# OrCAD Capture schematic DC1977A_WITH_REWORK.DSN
size A; title: -
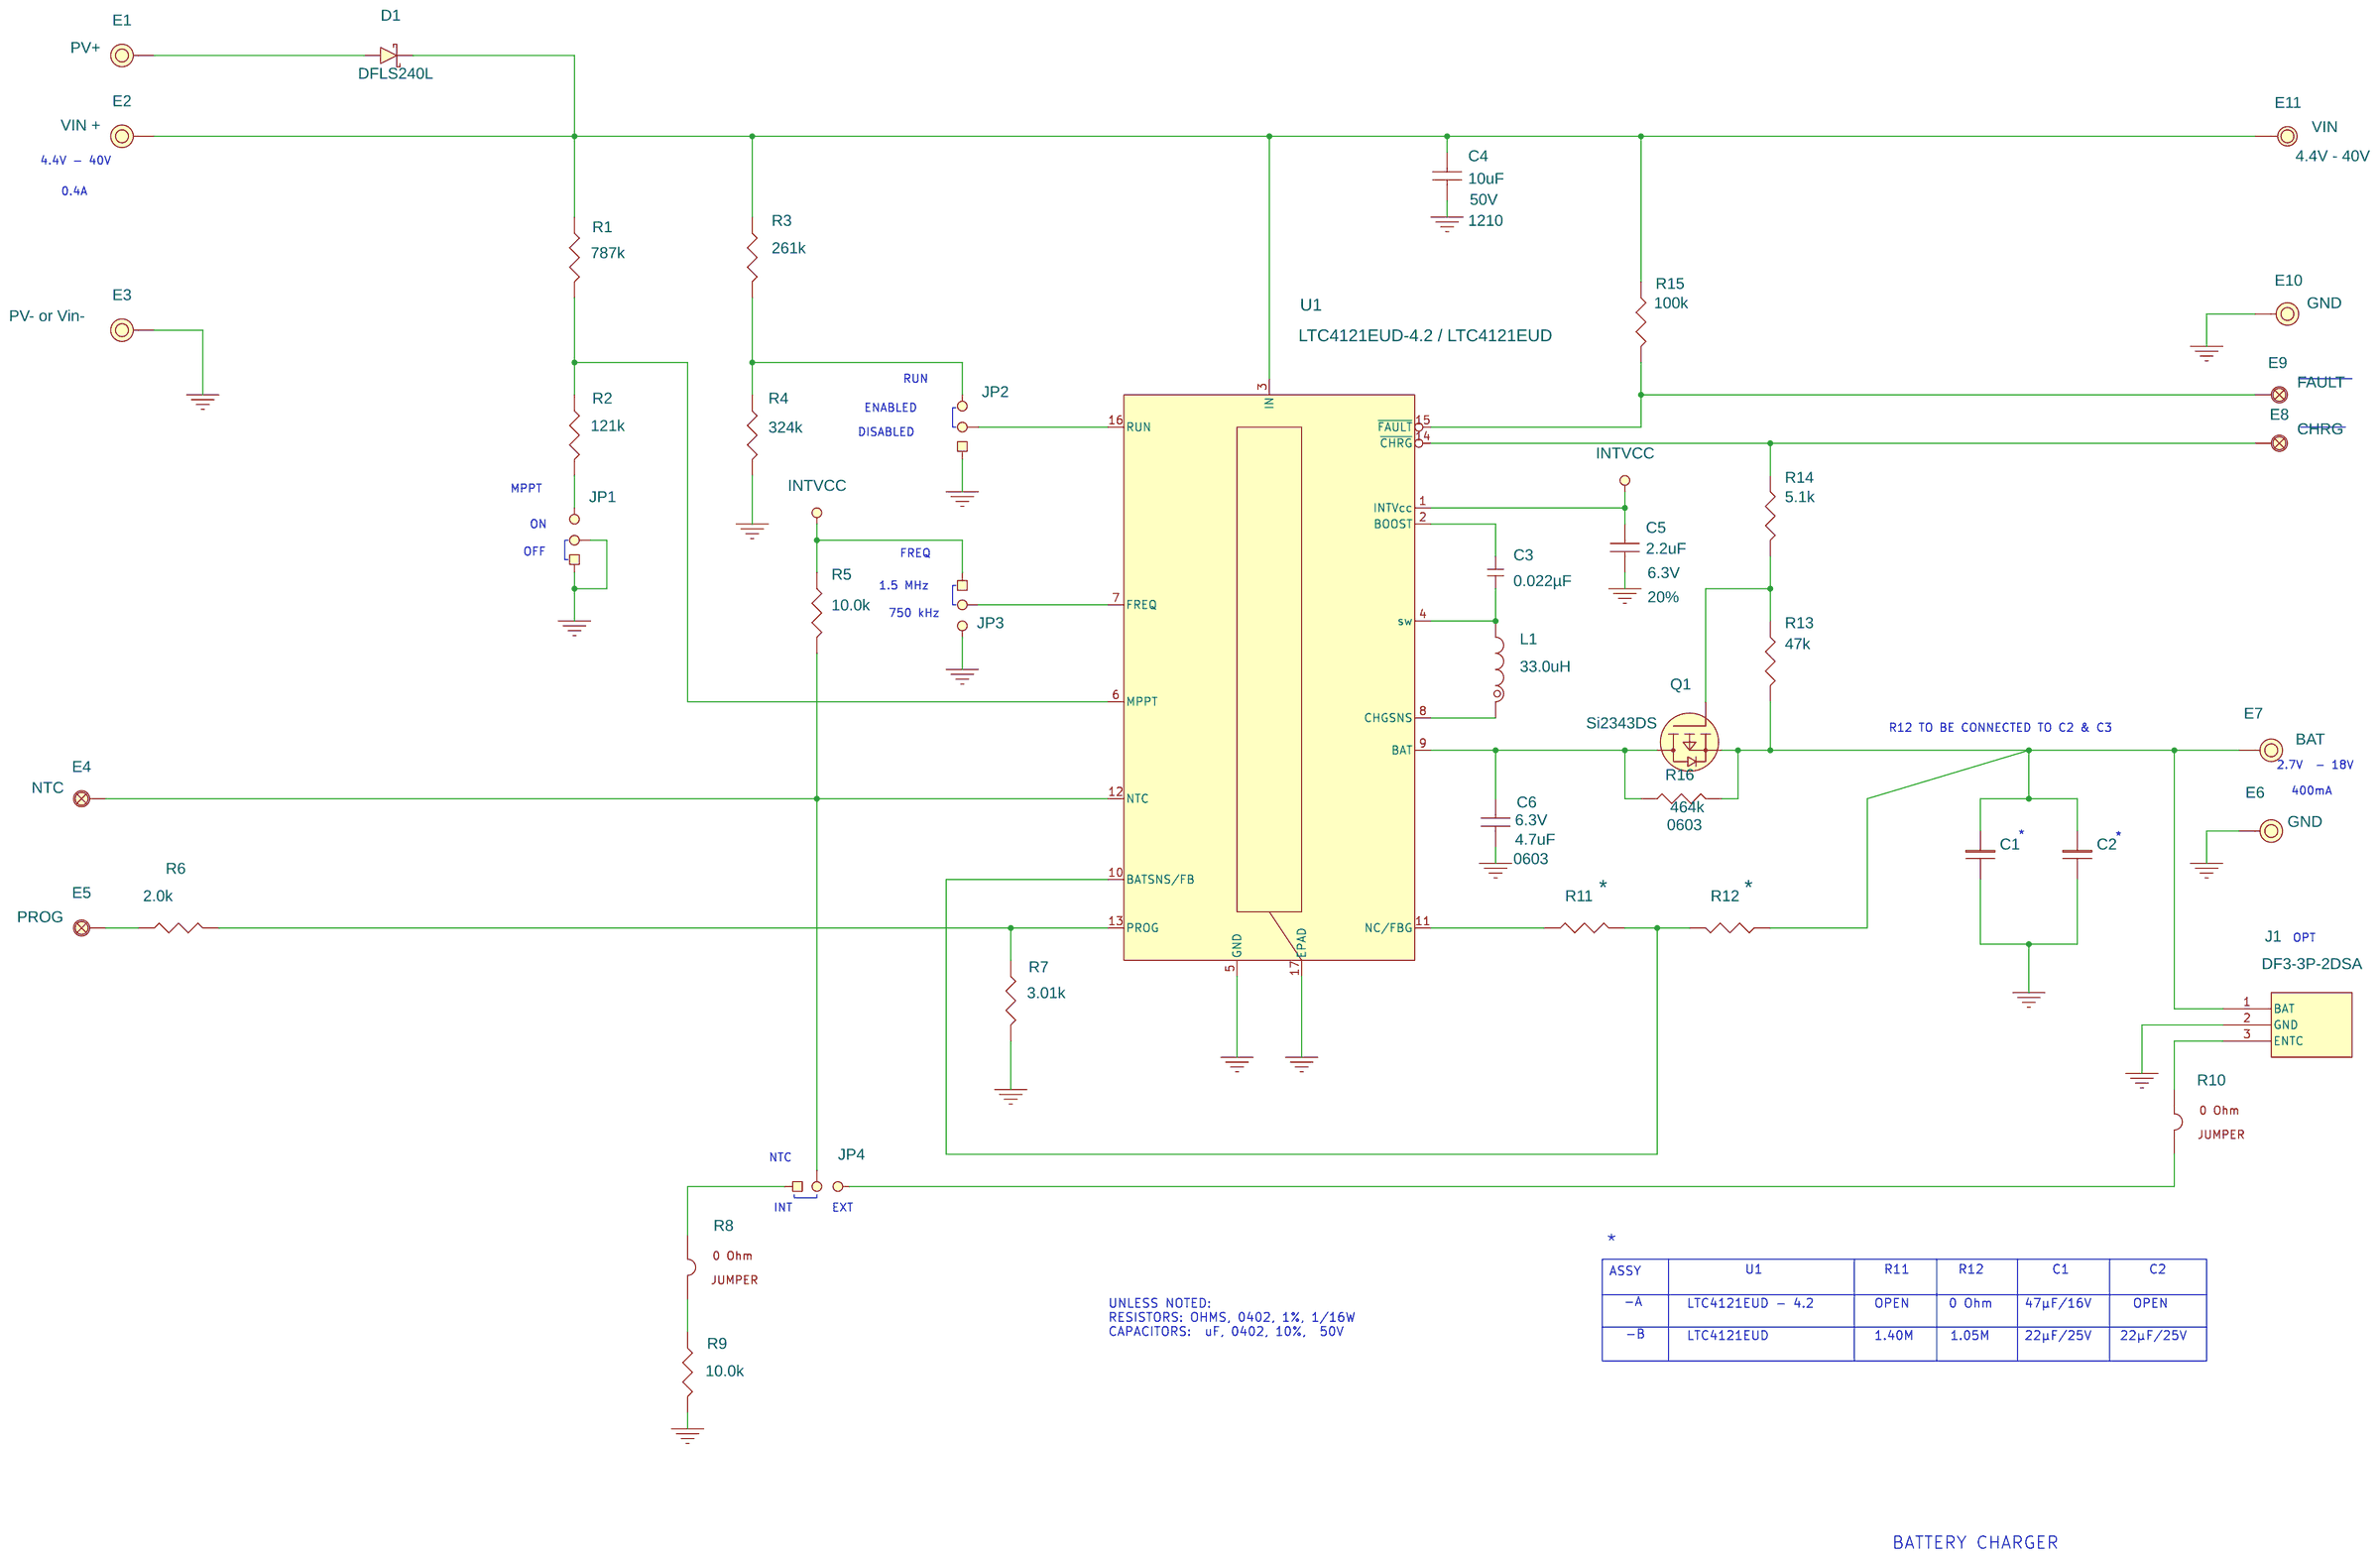
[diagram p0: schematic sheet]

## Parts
C1  22µF  [1210]
C2  22µF  [1210]
C3  0.022µF  [0402-SMALL]
C4  10uF  [CC0402N,CC0402L,CC0402M]
C5  2.2uF  [CC0402N,CC0402L,CC0402M]
C6  4.7uF  [CC0603N,CC0603L,CC0603M]
D1  DFLS240L  [PowerDI123]
E1  PV+  [MILL-MAX-2501-2]
E2  VIN +  [MILL-MAX-2501-2]
E3  PV- or Vin-  [MILL-MAX-2501-2]
E4  NTC  [MILL-MAX-2308]
E5  PROG  [MILL-MAX-2308]
E6  GND  [MILL-MAX-2501-2]
E7  BAT  [MILL-MAX-2501-2]
E8  CHRG  [MILL-MAX-2308]
E9  FAULT  [MILL-MAX-2308]
E10  GND  [MILL-MAX-2501-2]
E11  VIN  [MILL-MAX-2501-2]
J1  DF3-3P-2DSA  [DF32DSHEADER]
JP1  3 PINS, 2mm  [2MMJUMP3]
JP2  3 PINS, 2mm  [2MMJUMP3]
JP3  3 PINS, 2mm  [2MMJUMP3]
JP4  3 PINS, 2mm  [2MMJUMP3]
L1  33.0uH  [LPS4018]
Q1  Si2343DS  [SOT23]
R1  787k  [0402-SMALL]
R2  121k  [0402-SMALL]
R3  261k  [0402-SMALL]
R4  324k  [0402-SMALL]
R5  10.0k  [0402-SMALL]
R6  2.0k  [0402-SMALL]
R7  3.01k  [0402-SMALL]
R8  20m  [0402-SMALL]
R9  10.0k  [0402-SMALL]
R10  20m  [0402-SMALL]
R11  *  [0402-SMALL]
R12  *  [0402-SMALL]
R13  47k  [0402-SMALL]
R14  5.1k  [0402-SMALL]
R15  100k  [0402-SMALL]
R16  464k  [CR0603N]
U1  LTC4121EUD-4.2 / LTC4121EUD  [QFN(16)(UD)3MMX3MM]

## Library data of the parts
C1 C2 = GRM32ER61C476KE15L: VOLTAGE: 25V
C3 = VJ0402Y103JXXA_0
C4 = CAP: CAP.,10uF,X5R,50V,10%,1210; CLASS: DISCRETE; Dielectric Type: X5R; Manufacturer: TDK; Manufacturer PN: C3225X5R1H106K; Package Size: 1210; Rated Voltage: 50V; Tolerance: 10%
C5 = CAP: CAP.,2.2uF,X5R,6.3V,20%,0402; CLASS: DISCRETE; Dielectric Type: X5R; Manufacturer: MURATA; Manufacturer PN: GRM155R60J225ME15D; Package Size: 0402; Rated Voltage: 6.3V; Tolerance: 20%
C6 = CAP: CAP.,4.7uF,X5R,6.3V,20%,0603; CLASS: DISCRETE; Dielectric Type: X5R; Manufacturer: MURATA; Manufacturer PN: GRM188R60J475KE19D; Package Size: 0603; Rated Voltage: 6.3V; Tolerance: 10%
D1 = DFLS240L
E1-E3 E6 E10 = E_3
E4 E5 E8 E9 = TP_KEY_1502-2_0: 4th Part Field: MILL-MAX; 5th Part Field: 2308-2; 7th Part Field: TURRET, SIGNAL; 9th Part Field: EN1; Part Number: MILL-MAX 2308-2
E7 = E_3: TURRET
E11 = MillMax-2501-2: 10th Part Field: VBUS; 4th Part Field: MILL-MAX; 9th Part Field: 4.4V - 40V
J1 = CON3_1
JP1-JP4 = JP3X1_079_NO_6: 4TH PART FIELD: SAMTEC; 5TH PART FIELD: TMM-103-02-L-S; 7TH PART FIELD: HEADER; Part Number: TMM-103-02-L-S
L1 = LPS4018-333MLC
Q1 = Si2343DS
R1 = CRCW0402787KFKED
R2 = CRCW0402121KFKED
R3 = CRCW0402261KFKED
R4 = CRCW0402324KFKED
R5 R9 = CRCW040210K0FKED
R6 = CRCW04022K00JNED
R7 = CRCW04023K01FKED
R8 R10 = CRCW04020000Z0ED_0
R11 R12 = CRCW0402100KFKED
R13 = CRCW040247K0JNED
R14 = CRCW04025K10JNED
R15 = CRCW0402100KJNED
R16 = RES: RES, 464k, 1/10W, 1%, 0603; CLASS: DISCRETE; Manufacturer: Yageo; Manufacturer PN: RC0603FR-07464KL; Package Size: 0603; Rated Power: 1/10W; Tolerance: 1%
U1 = LTC4121EUD_2

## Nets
GND: C1.2 C2.2 C4.2 C5.2 C6.2 E3.1(A) E6.1(A) E10.1(A) J1.2(GND) JP1.1 JP1.2 JP2.1 JP3.3 R4.2(pin2) R7.2(pin2) R9.2(pin2) U1.5(GND) U1.17(EPAD)
INTVCC: C5.1 JP3.1 R5.1(pin1) U1.1(INTVcc)
N17194672: C1.1 C2.1 E7.1(A) J1.1(BAT) Q1.2(S) R12.1(pin1) R13.2(pin2) R16.2
N17195283: JP4.1 R8.1(pin1)
N17197391: J1.3(ENTC) R10.1(pin1)
N17265375: R8.2(pin2) R9.1(pin1)
N17301488: E4.1 JP4.2 R5.2(pin2) U1.12(NTC)
N17334729: C4.1 D1.1 E2.1(A) E11.1 R1.1(pin1) R3.1(pin1) R15.1(pin1) U1.3(IN)
N17342445: JP2.2 U1.16(RUN)
N17342929: C3.2 L1.2 U1.4(sw)
N17342968: L1.1 U1.8(CHGSNS)
N17343033: C3.1 U1.2(BOOST)
N17343389: E8.1 R14.1(pin1) U1.14(~{CHRG})
N17343421: E9.1 R15.2(pin2) U1.15(~{FAULT})
N17344705: JP3.2 U1.7(FREQ)
N17345301: E5.1 R6.1(pin1)
N17345322: R6.2(pin2) R7.1(pin1) U1.13(PROG)
N17346309: D1.2 E1.1(A)
N17350124: R11.1(pin1) U1.11(NC/FBG)
N17354111: R11.2(pin2) R12.2(pin2) U1.10(BATSNS/FB)
N17359045: JP4.3 R10.2(pin2)
N17360927: JP2.3 R3.2(pin2) R4.1(pin1)
N17464625: R1.2(pin2) R2.1(pin1) U1.6(MPPT)
N17475720: JP1.3 R2.2(pin2)
N17479021: C6.1 Q1.3(D) R16.1 U1.9(BAT)
N17498056: Q1.1(G) R13.1(pin1) R14.2(pin2)

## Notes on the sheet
- 4.4V - 40V
- 0.4A
- RUN
- ENABLED
- DISABLED
- MPPT
- ON
- OFF
- FREQ
- 1.5 MHz
- 750 kHz
- R12 TO BE CONNECTED TO C2 & C3
- 2.7V  - 18V
- 400mA
- *
- *
- OPT
- NTC
- INT
- EXT
- *
- ASSY
- U1
- R11
- R12
- C1
- C2
- UNLESS NOTED:
  RESISTORS: OHMS, 0402, 1%, 1/16W
  CAPACITORS:  uF, 0402, 10%,  50V
- -A
- LTC4121EUD - 4.2
- OPEN
- 0 Ohm
- 47µF/16V
- OPEN
- -B
- LTC4121EUD
- 1.40M
- 1.05M
- 22µF/25V
- 22µF/25V
- BATTERY CHARGER
